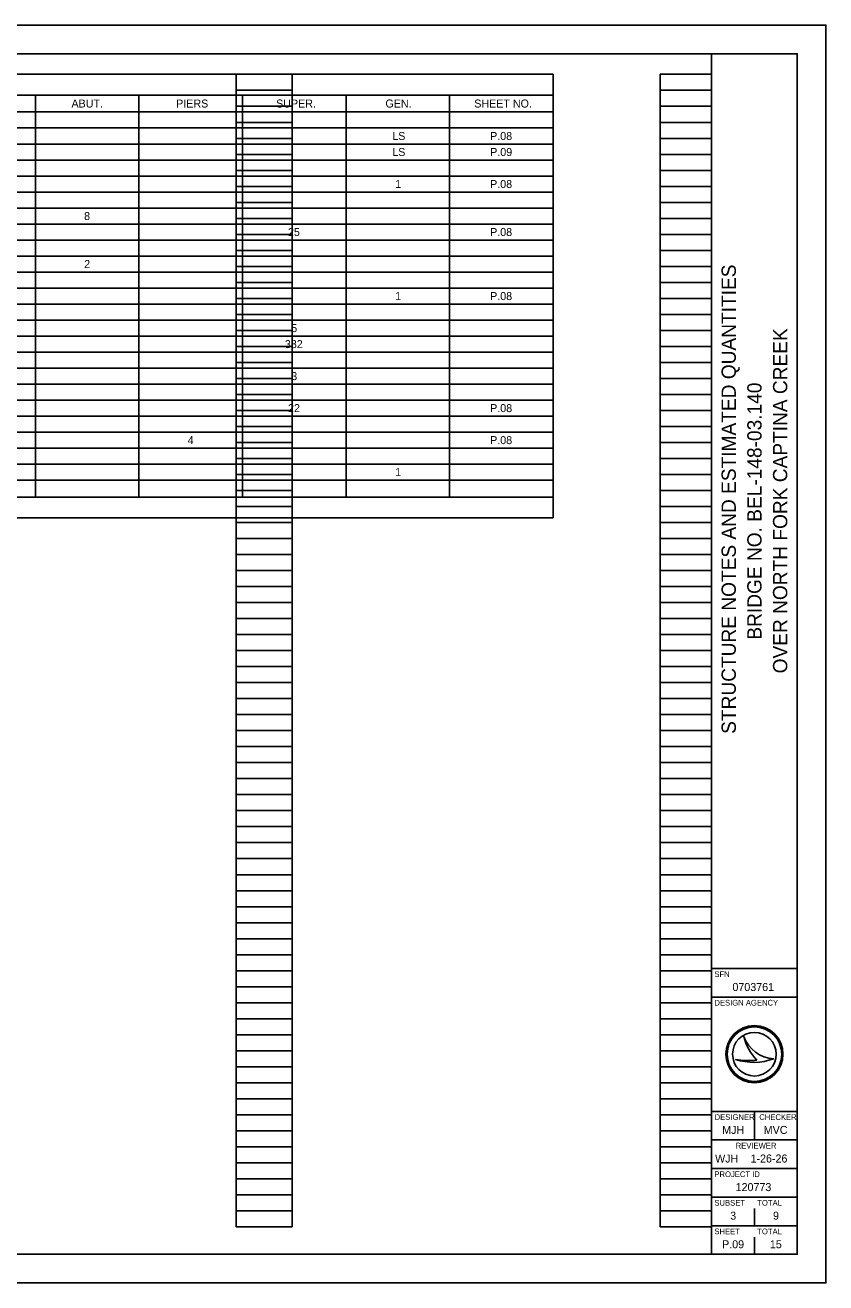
# Model space of a CAD drawing. Extents: x 0 to 34, y 0 to 22.
# Drawn here: x 19.99 to 34, y 0 to 22 of the extents above; entities that cross this region are included whole.
import ezdxf

# ---------------------------------------------------------------- set-up
doc = ezdxf.new("R2010")
doc.units = 0
for name, color, linetype in [('Default', 7, 'Continuous'), ('SH_Border', 7, 'Continuous'), ('SH_Cut_Line', 7, 'Continuous'), ('SH_Data', 7, 'Continuous')]:
    doc.layers.add(name, color=color, linetype=linetype)

msp = doc.modelspace()

# ---------------------------------------------------------------- linework, layer by layer
at = {"layer": 'Default'}
for p, q in [((4.274, 21.14), (29.226, 21.14)), ((29.226, 21.14), (29.226, 13.382)), ((4.274, 20.778), (29.226, 20.778)), ((20.168, 20.778), (20.168, 13.745)), ((21.979, 20.778), (21.979, 13.745)), ((23.791, 20.778), (23.791, 13.745)), ((25.603, 20.778), (25.603, 13.745)), ((27.415, 20.778), (27.415, 13.745)), ((4.274, 20.481), (29.226, 20.481)), ((4.274, 20.201), (29.226, 20.201)), ((4.274, 19.921), (29.226, 19.921)), ((4.274, 19.641), (29.226, 19.641)), ((4.274, 19.361), (29.226, 19.361)), ((4.274, 19.081), (29.226, 19.081)), ((4.274, 18.801), (29.226, 18.801)), ((4.274, 18.521), (29.226, 18.521)), ((4.274, 18.241), (29.226, 18.241)), ((4.274, 17.961), (29.226, 17.961)), ((4.274, 17.681), (29.226, 17.681)), ((4.274, 17.401), (29.226, 17.401)), ((4.274, 17.121), (29.226, 17.121)), ((4.274, 16.841), (29.226, 16.841)), ((4.274, 16.561), (29.226, 16.561)), ((4.274, 16.281), (29.226, 16.281)), ((4.274, 16.001), (29.226, 16.001)), ((4.274, 15.721), (29.226, 15.721)), ((4.274, 15.441), (29.226, 15.441)), ((4.274, 15.161), (29.226, 15.161)), ((4.274, 14.881), (29.226, 14.881)), ((4.274, 14.601), (29.226, 14.601)), ((4.274, 14.321), (29.226, 14.321)), ((4.274, 14.041), (29.226, 14.041)), ((4.274, 13.745), (29.226, 13.745)), ((4.274, 13.382), (29.226, 13.382))]:
    msp.add_line(p, q, dxfattribs=at)
at = {"layer": 'SH_Border'}
for p, q in [((32, 0.5), (32, 21.5)), ((32, 5.5), (33.5, 5.5)), ((32, 5), (33.5, 5)), ((32, 3), (33.5, 3)), ((32.75, 3), (32.75, 2.5)), ((32, 2.5), (33.5, 2.5)), ((32, 2), (33.5, 2)), ((32, 1.5), (33.5, 1.5)), ((32, 1), (33.5, 1))]:
    msp.add_line(p, q, dxfattribs=at)
msp.add_lwpolyline([(1.5, 21.5), (33.5, 21.5), (33.5, 0.5), (1.5, 0.5)], close=True, dxfattribs=at)
at = {"layer": 'SH_Cut_Line'}
msp.add_lwpolyline([(0, 0), (34, 0), (34, 22), (0, 22)], close=True, dxfattribs=at)
at = {"layer": 'SH_Data'}
for p, q in [((23.68, 0.98), (23.68, 21.14)), ((23.68, 21.14), (24.66, 21.14)), ((24.66, 0.98), (24.66, 21.14)), ((31.1, 0.98), (31.1, 21.14)), ((31.1, 21.14), (32, 21.14)), ((32, 0.98), (32, 21.14)), ((23.68, 20.86), (24.66, 20.86)), ((31.1, 20.86), (32, 20.86)), ((23.68, 20.58), (24.66, 20.58)), ((31.1, 20.58), (32, 20.58)), ((23.68, 20.3), (24.66, 20.3)), ((31.1, 20.3), (32, 20.3)), ((23.68, 20.02), (24.66, 20.02)), ((31.1, 20.02), (32, 20.02)), ((23.68, 19.74), (24.66, 19.74)), ((31.1, 19.74), (32, 19.74)), ((23.68, 19.46), (24.66, 19.46)), ((31.1, 19.46), (32, 19.46)), ((23.68, 19.18), (24.66, 19.18)), ((31.1, 19.18), (32, 19.18)), ((23.68, 18.9), (24.66, 18.9)), ((31.1, 18.9), (32, 18.9)), ((23.68, 18.62), (24.66, 18.62)), ((31.1, 18.62), (32, 18.62)), ((23.68, 18.34), (24.66, 18.34)), ((31.1, 18.34), (32, 18.34)), ((23.68, 18.06), (24.66, 18.06)), ((31.1, 18.06), (32, 18.06)), ((23.68, 17.78), (24.66, 17.78)), ((31.1, 17.78), (32, 17.78)), ((23.68, 17.5), (24.66, 17.5)), ((31.1, 17.5), (32, 17.5)), ((23.68, 17.22), (24.66, 17.22)), ((31.1, 17.22), (32, 17.22)), ((23.68, 16.94), (24.66, 16.94)), ((31.1, 16.94), (32, 16.94)), ((23.68, 16.66), (24.66, 16.66)), ((31.1, 16.66), (32, 16.66)), ((23.68, 16.38), (24.66, 16.38)), ((31.1, 16.38), (32, 16.38)), ((23.68, 16.1), (24.66, 16.1)), ((31.1, 16.1), (32, 16.1)), ((23.68, 15.82), (24.66, 15.82)), ((31.1, 15.82), (32, 15.82)), ((23.68, 15.54), (24.66, 15.54)), ((31.1, 15.54), (32, 15.54)), ((23.68, 15.26), (24.66, 15.26)), ((31.1, 15.26), (32, 15.26)), ((23.68, 14.98), (24.66, 14.98)), ((31.1, 14.98), (32, 14.98)), ((23.68, 14.7), (24.66, 14.7)), ((31.1, 14.7), (32, 14.7)), ((23.68, 14.42), (24.66, 14.42)), ((31.1, 14.42), (32, 14.42)), ((23.68, 14.14), (24.66, 14.14)), ((31.1, 14.14), (32, 14.14)), ((23.68, 13.86), (24.66, 13.86)), ((31.1, 13.86), (32, 13.86)), ((23.68, 13.58), (24.66, 13.58)), ((31.1, 13.58), (32, 13.58)), ((23.68, 13.3), (24.66, 13.3)), ((31.1, 13.3), (32, 13.3)), ((23.68, 13.02), (24.66, 13.02)), ((31.1, 13.02), (32, 13.02)), ((23.68, 12.74), (24.66, 12.74)), ((31.1, 12.74), (32, 12.74)), ((23.68, 12.46), (24.66, 12.46)), ((31.1, 12.46), (32, 12.46)), ((23.68, 12.18), (24.66, 12.18)), ((31.1, 12.18), (32, 12.18)), ((23.68, 11.9), (24.66, 11.9)), ((31.1, 11.9), (32, 11.9)), ((23.68, 11.62), (24.66, 11.62)), ((31.1, 11.62), (32, 11.62)), ((23.68, 11.34), (24.66, 11.34)), ((31.1, 11.34), (32, 11.34)), ((23.68, 11.06), (24.66, 11.06)), ((31.1, 11.06), (32, 11.06)), ((23.68, 10.78), (24.66, 10.78)), ((31.1, 10.78), (32, 10.78)), ((23.68, 10.5), (24.66, 10.5)), ((31.1, 10.5), (32, 10.5)), ((23.68, 10.22), (24.66, 10.22)), ((31.1, 10.22), (32, 10.22)), ((23.68, 9.94), (24.66, 9.94)), ((31.1, 9.94), (32, 9.94)), ((23.68, 9.66), (24.66, 9.66)), ((31.1, 9.66), (32, 9.66)), ((23.68, 9.38), (24.66, 9.38)), ((31.1, 9.38), (32, 9.38)), ((23.68, 9.1), (24.66, 9.1)), ((31.1, 9.1), (32, 9.1)), ((23.68, 8.82), (24.66, 8.82)), ((31.1, 8.82), (32, 8.82)), ((23.68, 8.54), (24.66, 8.54)), ((31.1, 8.54), (32, 8.54)), ((23.68, 8.26), (24.66, 8.26)), ((31.1, 8.26), (32, 8.26)), ((23.68, 7.98), (24.66, 7.98)), ((31.1, 7.98), (32, 7.98)), ((23.68, 7.7), (24.66, 7.7)), ((31.1, 7.7), (32, 7.7)), ((23.68, 7.42), (24.66, 7.42)), ((31.1, 7.42), (32, 7.42)), ((23.68, 7.14), (24.66, 7.14)), ((31.1, 7.14), (32, 7.14)), ((23.68, 6.86), (24.66, 6.86)), ((31.1, 6.86), (32, 6.86)), ((23.68, 6.58), (24.66, 6.58)), ((31.1, 6.58), (32, 6.58)), ((23.68, 6.3), (24.66, 6.3)), ((31.1, 6.3), (32, 6.3)), ((23.68, 6.02), (24.66, 6.02)), ((31.1, 6.02), (32, 6.02)), ((23.68, 5.74), (24.66, 5.74)), ((31.1, 5.74), (32, 5.74)), ((23.68, 5.46), (24.66, 5.46)), ((31.1, 5.46), (32, 5.46)), ((23.68, 5.18), (24.66, 5.18)), ((31.1, 5.18), (32, 5.18)), ((23.68, 4.9), (24.66, 4.9)), ((31.1, 4.9), (32, 4.9)), ((23.68, 4.62), (24.66, 4.62)), ((31.1, 4.62), (32, 4.62)), ((23.68, 4.34), (24.66, 4.34)), ((31.1, 4.34), (32, 4.34)), ((32.567, 4.31), (32.567, 4.31)), ((23.68, 4.06), (24.66, 4.06)), ((31.1, 4.06), (32, 4.06)), ((32.75, 4), (32.75, 4)), ((23.68, 3.78), (24.66, 3.78)), ((31.1, 3.78), (32, 3.78)), ((32.417, 3.91), (32.417, 3.91)), ((33.087, 3.919), (33.087, 3.919)), ((23.68, 3.5), (24.66, 3.5)), ((31.1, 3.5), (32, 3.5)), ((23.68, 3.22), (24.66, 3.22)), ((31.1, 3.22), (32, 3.22)), ((23.68, 2.94), (24.66, 2.94)), ((31.1, 2.94), (32, 2.94)), ((23.68, 2.66), (24.66, 2.66)), ((31.1, 2.66), (32, 2.66)), ((23.68, 2.38), (24.66, 2.38)), ((31.1, 2.38), (32, 2.38)), ((23.68, 2.1), (24.66, 2.1)), ((31.1, 2.1), (32, 2.1)), ((23.68, 1.82), (24.66, 1.82)), ((31.1, 1.82), (32, 1.82)), ((23.68, 1.54), (24.66, 1.54)), ((31.1, 1.54), (32, 1.54)), ((23.68, 1.26), (24.66, 1.26)), ((31.1, 1.26), (32, 1.26)), ((32.75, 1), (32.75, 1.3)), ((23.68, 0.98), (24.66, 0.98)), ((31.1, 0.98), (32, 0.98)), ((32.375, 0.675), (32.375, 0.675)), ((32.75, 0.5), (32.75, 0.8))]:
    msp.add_line(p, q, dxfattribs=at)
for radius in [0.5, 0.477, 0.477, 0.382]:
    msp.add_circle((32.75, 4), radius, dxfattribs=at)
for centre, radius, start, end in [((33.116, 4.498), 0.58, 198.9257, 198.9319), ((33.347, 4.47), 0.796, 191.6379, 191.6421), ((33.116, 4.498), 0.58, 198.9319, 267.1657), ((33.347, 4.47), 0.796, 191.6421, 226.0947), ((32.739, 4.87), 1.013, 251.4576, 290.0832), ((32.648, 5.154), 1.266, 259.4964, 259.4995), ((32.739, 4.87), 1.013, 251.4527, 251.4576), ((32.648, 5.154), 1.266, 259.4995, 276.6672)]:
    msp.add_arc(centre, radius, start, end, dxfattribs=at)

# ---------------------------------------------------------------- texts
at = {"layer": 'Default'}
for s, p in [('ABUT.', (20.799, 20.559)), ('PIERS', (22.631, 20.559)), ('SUPER.', (24.38, 20.559)), ('GEN.', (26.293, 20.559)), ('SHEET NO.', (27.847, 20.559)), ('LS', (26.413, 19.991)), ('P.08', (28.125, 19.991)), ('LS', (26.413, 19.711)), ('P.09', (28.126, 19.711)), ('1', (26.463, 19.151)), ('P.08', (28.125, 19.151)), ('8', (21.019, 18.591)), ('25', (24.588, 18.311)), ('P.08', (28.125, 18.311)), ('2', (21.021, 17.751)), ('1', (26.463, 17.191)), ('P.08', (28.125, 17.191)), ('5', (24.644, 16.631)), ('382', (24.533, 16.351)), ('3', (24.645, 15.791)), ('22', (24.589, 15.231)), ('P.08', (28.125, 15.231)), ('4', (22.833, 14.671)), ('P.08', (28.125, 14.671)), ('1', (26.463, 14.111))]:
    msp.add_text(s, height=0.14, dxfattribs=at).set_placement(p)
at = {"layer": 'SH_Data'}
for s, p in [('STRUCTURE NOTES AND ESTIMATED QUANTITIES', (32.425, 9.603)), ('OVER NORTH FORK CAPTINA CREEK', (33.325, 10.661)), ('BRIDGE NO. BEL-148-03.140', (32.875, 11.251))]:
    msp.add_text(s, height=0.25, rotation=90, dxfattribs=at).set_placement(p)
for s, height, p in [('SFN', 0.1, (32.05, 5.35)), ('0703761', 0.14, (32.365, 5.105)), ('DESIGN AGENCY', 0.1, (32.05, 4.85)), ('DESIGNER', 0.1, (32.054, 2.85)), ('CHECKER', 0.1, (32.835, 2.85)), ('MJH', 0.14, (32.186, 2.605)), ('MVC', 0.14, (32.913, 2.605)), ('REVIEWER', 0.1, (32.422, 2.35)), ('WJH', 0.14, (32.062, 2.105)), ('1-26-26', 0.14, (32.682, 2.105)), ('PROJECT ID', 0.1, (32.05, 1.85)), ('120773', 0.14, (32.421, 1.605)), ('SUBSET', 0.1, (32.05, 1.35)), ('TOTAL', 0.1, (32.8, 1.35)), ('3', 0.14, (32.326, 1.105)), ('9', 0.14, (33.075, 1.105)), ('SHEET', 0.1, (32.05, 0.85)), ('TOTAL', 0.1, (32.8, 0.85)), ('P.09', 0.14, (32.184, 0.605)), ('15', 0.14, (33.02, 0.605))]:
    msp.add_text(s, height=height, dxfattribs=at).set_placement(p)

doc.saveas('drawing.dxf')
